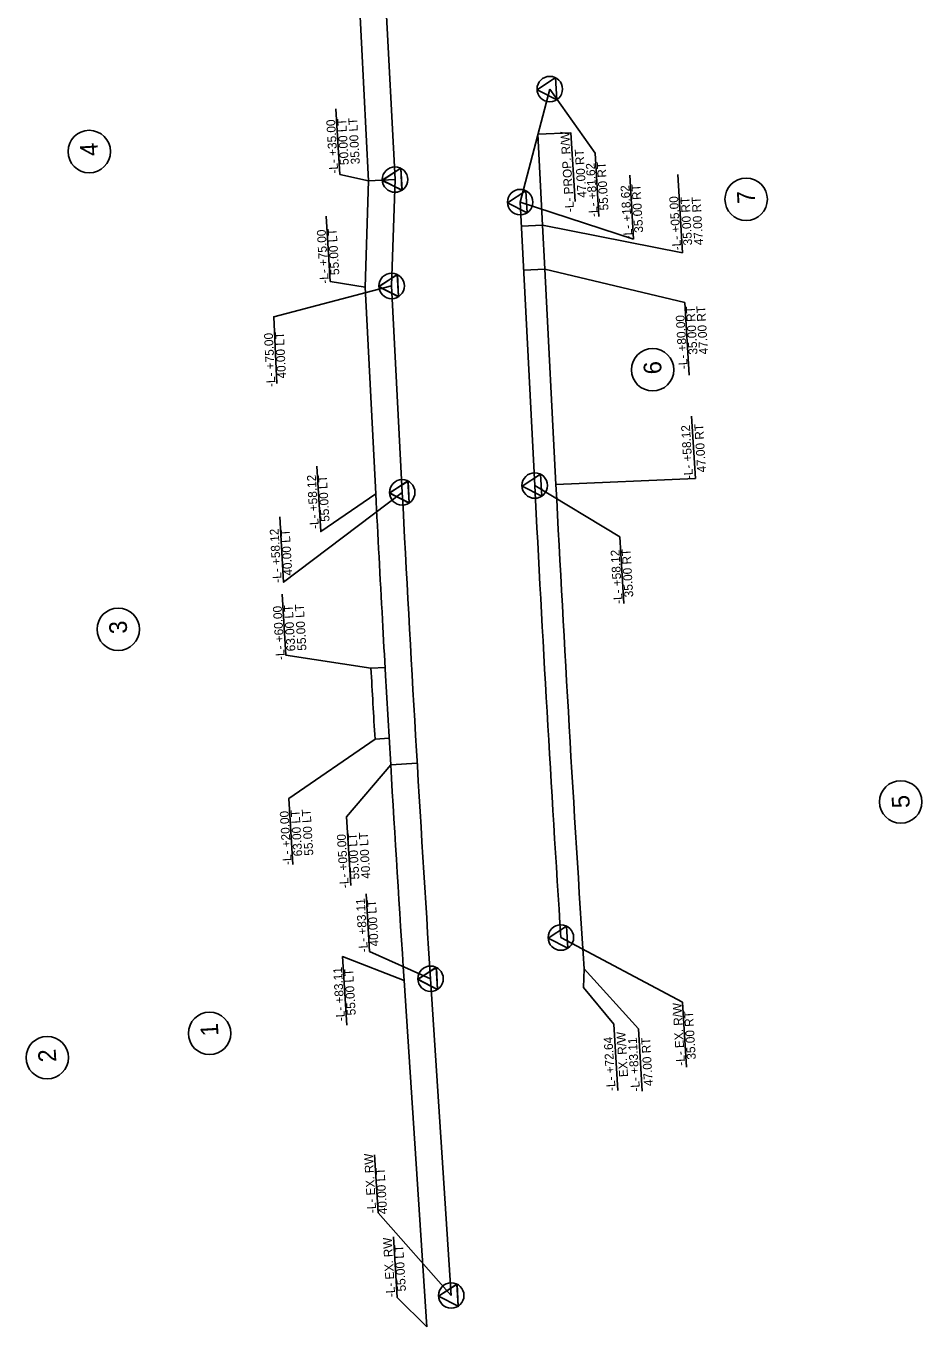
# Model space of a CAD drawing. Extents: x 2368169 to 2369183, y 801414 to 808542.
# Drawn here: x 2368677 to 2369183, y 801414 to 802150 of the extents above; entities that cross this region are included whole.
import ezdxf

# ---------------------------------------------------------------- set-up
doc = ezdxf.new("R2010")
doc.units = 0
for name, color, linetype in [('Prop Easement Construction', 7, 'Continuous'), ('Prop Easement Construction Station Offsets', 7, 'Continuous'), ('Prop Easement Permanent Drainage', 7, 'Continuous'), ('Prop Easement Permanent Drainage Station Offsets', 7, 'Continuous'), ('Prop Easement Permanent Drainage Utility', 7, 'Continuous'), ('Prop Easement Permanent Drainage Utility Station Offsets', 7, 'Continuous'), ('Prop Easement Permanent Utility', 7, 'Continuous'), ('Prop Easement Permanent Utility Station Offsets', 7, 'Continuous'), ('Prop Parcel Number CELL', 7, 'Continuous'), ('Prop Parcel Number Text', 7, 'Continuous'), ('Prop ROW Marker CELL', 7, 'Continuous'), ('Prop ROW RW Lines', 7, 'Continuous'), ('Prop ROW Station Offsets', 7, 'Continuous')]:
    doc.layers.add(name, color=color, linetype=linetype)

msp = doc.modelspace()

# ---------------------------------------------------------------- linework, layer by layer
at = {"layer": 'Prop Easement Construction'}
for p, q in [((2368968.57, 802037.5), (2368965.94, 802088.86)), ((2368976.11, 801890.82), (2368969.86, 802012.53)), ((2368992.07, 801616.92), (2368991.68, 801606.39))]:
    msp.add_line(p, q, dxfattribs=at)
msp.add_arc((2388902.84, 802914.38), 19953, 182.940485, 183.728337, dxfattribs=at)
at = {"layer": 'Prop Easement Construction Station Offsets'}
for p, q in [((2369052.79, 801929.37), (2369054.93, 801894.11)), ((2369054.93, 801894.11), (2368976.11, 801890.82))]:
    msp.add_line(p, q, dxfattribs=at)
for points in [[(2368986.96, 802050.94), (2368984.61, 802089.64), (2368965.94, 802088.86)], [(2369024.85, 801547.71), (2369022.72, 801582.85), (2368992.07, 801616.92)], [(2369011.09, 801548.02), (2369008.81, 801585.56), (2368991.68, 801606.39)]]:
    msp.add_lwpolyline(points, dxfattribs=at)
at = {"layer": 'Prop Easement Permanent Drainage'}
for p, q in [((2368968.57, 802037.5), (2368956.59, 802036.88)), ((2368969.86, 802012.53), (2368968.57, 802037.5)), ((2368969.86, 802012.53), (2368957.87, 802011.92)), ((2368879.53, 801787.33), (2368871.54, 801786.88)), ((2368881.82, 801747.29), (2368873.84, 801746.82))]:
    msp.add_line(p, q, dxfattribs=at)
msp.add_arc((2388902.84, 802914.38), 20063, 183.221583, 183.336175, dxfattribs=at)
at = {"layer": 'Prop Easement Permanent Drainage Station Offsets'}
for p, q in [((2369047.63, 802021.89), (2369044.96, 802066.15)), ((2368968.57, 802037.5), (2369047.63, 802021.89)), ((2368969.86, 802012.53), (2369049.01, 801993.71)), ((2369049.01, 801993.71), (2369051.48, 801952.58))]:
    msp.add_line(p, q, dxfattribs=at)
for points in [[(2368821.28, 801828.73), (2368823.35, 801794.29), (2368871.54, 801786.88)], [(2368827.39, 801675.91), (2368825.14, 801713.27), (2368873.84, 801746.82)]]:
    msp.add_lwpolyline(points, dxfattribs=at)
at = {"layer": 'Prop Easement Permanent Drainage Utility'}
for p, q in [((2368868.25, 802002.31), (2368870.16, 802062.48)), ((2368870.19, 802062.49), (2368885.14, 802063.25)), ((2368874.24, 801885.58), (2368868.25, 802002.31)), ((2368882.71, 801732.27), (2368897.68, 801733.16))]:
    msp.add_line(p, q, dxfattribs=at)
for start, end in [(182.940485, 183.144357), (183.144357, 183.234563), (183.234563, 183.379147)]:
    msp.add_arc((2388902.84, 802914.38), 20055, start, end, dxfattribs=at)
at = {"layer": 'Prop Easement Permanent Drainage Utility Station Offsets'}
for p, q in [((2368846.18, 802042.61), (2368848.41, 802005.55)), ((2368848.41, 802005.55), (2368868.25, 802002.31))]:
    msp.add_line(p, q, dxfattribs=at)
for points in [[(2368851.72, 802103.18), (2368853.95, 802066.12), (2368870.16, 802062.48)], [(2368840.89, 801901.21), (2368843.12, 801864.16), (2368874.24, 801885.58)], [(2368860.1, 801664.06), (2368857.77, 801702.9), (2368882.71, 801732.27)]]:
    msp.add_lwpolyline(points, dxfattribs=at)
at = {"layer": 'Prop Easement Permanent Utility'}
for p, q in [((2368870.16, 802062.48), (2368850.79, 802439.57)), ((2368903.05, 801414.3), (2368890.28, 801610.28))]:
    msp.add_line(p, q, dxfattribs=at)
msp.add_arc((2388902.84, 802914.38), 20055, 183.379147, 183.728337, dxfattribs=at)
at = {"layer": 'Prop Easement Permanent Utility Station Offsets'}
for points in [[(2368857.85, 801584.98), (2368855.51, 801623.83), (2368890.28, 801610.28)], [(2368884.27, 801465.25), (2368886.37, 801430.88), (2368903.05, 801414.3)]]:
    msp.add_lwpolyline(points, dxfattribs=at)
at = {"layer": 'Prop Parcel Number CELL'}
for p, q in [((2368712.29, 802079.1), (2368712.29, 802079.1)), ((2369083.65, 802052.08), (2369083.65, 802052.08)), ((2369030.77, 801955.69), (2369030.77, 801955.69)), ((2368728.69, 801808.88), (2368728.69, 801808.88)), ((2369171.02, 801711.28), (2369171.02, 801711.28)), ((2368780.32, 801580.35), (2368780.32, 801580.35)), ((2368688.56, 801566.63), (2368688.56, 801566.63))]:
    msp.add_line(p, q, dxfattribs=at)
for centre in [(2368712.29, 802079.1), (2369083.65, 802052.08), (2369030.77, 801955.69), (2368728.69, 801808.88), (2369171.02, 801711.28), (2368780.32, 801580.35), (2368688.56, 801566.63)]:
    msp.add_circle(centre, 12, dxfattribs=at)
at = {"layer": 'Prop ROW Marker CELL'}
for p, q in [((2368972.63, 802114.43), (2368972.63, 802114.43)), ((2368972.63, 802114.43), (2368972.63, 802114.43)), ((2368885.14, 802063.25), (2368885.14, 802063.25)), ((2368885.14, 802063.25), (2368885.14, 802063.25)), ((2368955.89, 802050.49), (2368955.89, 802050.49)), ((2368955.89, 802050.49), (2368955.89, 802050.49)), ((2368883.23, 802003.08), (2368883.23, 802003.08)), ((2368883.23, 802003.08), (2368883.23, 802003.08)), ((2368964.12, 801890.2), (2368964.12, 801890.2)), ((2368964.12, 801890.2), (2368964.12, 801890.2)), ((2368889.22, 801886.35), (2368889.22, 801886.35)), ((2368889.22, 801886.35), (2368889.22, 801886.35)), ((2368978.9, 801634.55), (2368978.9, 801634.55)), ((2368978.9, 801634.55), (2368978.9, 801634.55)), ((2368905.25, 801611.26), (2368905.25, 801611.26)), ((2368905.25, 801611.26), (2368905.25, 801611.26)), ((2368916.92, 801432.11), (2368916.92, 801432.11)), ((2368916.92, 801432.11), (2368916.92, 801432.11))]:
    msp.add_line(p, q, dxfattribs=at)
for points in [[(2368976.6, 802108.41), (2368965.44, 802114), (2368975.85, 802120.89)], [(2368976.6, 802108.41), (2368965.44, 802114), (2368975.85, 802120.89)], [(2368889.02, 802057.17), (2368877.95, 802062.93), (2368888.46, 802069.66)], [(2368889.11, 802057.23), (2368877.96, 802062.82), (2368888.36, 802069.71)], [(2368959.86, 802044.46), (2368948.7, 802050.05), (2368959.11, 802056.94)], [(2368959.86, 802044.46), (2368948.7, 802050.05), (2368959.11, 802056.94)], [(2368887.1, 801996.99), (2368876.03, 802002.75), (2368886.54, 802009.48)], [(2368887.2, 801997.05), (2368876.04, 802002.64), (2368886.44, 802009.53)], [(2368968.09, 801884.18), (2368956.94, 801889.77), (2368967.34, 801896.65)], [(2368968.09, 801884.18), (2368956.94, 801889.77), (2368967.34, 801896.65)], [(2368893.1, 801880.27), (2368882.03, 801886.03), (2368892.54, 801892.76)], [(2368893.19, 801880.33), (2368882.04, 801885.92), (2368892.44, 801892.81)], [(2368982.87, 801628.53), (2368971.71, 801634.12), (2368982.12, 801641)], [(2368982.87, 801628.53), (2368971.71, 801634.12), (2368982.12, 801641)], [(2368909.22, 801605.24), (2368898.06, 801610.83), (2368908.47, 801617.71)], [(2368909.13, 801605.18), (2368898.06, 801610.94), (2368908.57, 801617.66)], [(2368920.8, 801426.03), (2368909.73, 801431.79), (2368920.24, 801438.52)], [(2368920.89, 801426.09), (2368909.74, 801431.68), (2368920.14, 801438.57)]]:
    msp.add_lwpolyline(points, close=True, dxfattribs=at)
for centre in [(2368972.63, 802114.43), (2368885.14, 802063.25), (2368955.89, 802050.49), (2368883.23, 802003.08), (2368964.12, 801890.2), (2368889.22, 801886.35), (2368978.9, 801634.55), (2368905.25, 801611.26), (2368916.92, 801432.11)]:
    msp.add_circle(centre, 7.2, dxfattribs=at)
at = {"layer": 'Prop ROW RW Lines'}
for p, q in [((2368885.14, 802063.25), (2368865.77, 802440.34)), ((2368972.63, 802114.43), (2368955.89, 802050.49)), ((2368883.23, 802003.08), (2368885.14, 802063.25)), ((2368964.12, 801890.2), (2368955.89, 802050.49)), ((2368889.22, 801886.35), (2368883.23, 802003.08)), ((2368916.92, 801432.11), (2368905.25, 801611.26))]:
    msp.add_line(p, q, dxfattribs=at)
for radius, end in [(19965, 183.675386), (20040, 183.728337)]:
    msp.add_arc((2388902.84, 802914.38), radius, 182.940485, end, dxfattribs=at)
at = {"layer": 'Prop ROW Station Offsets'}
for p, q in [((2368998.26, 802078.18), (2368972.63, 802114.43)), ((2369000.42, 802042.31), (2368998.26, 802078.18)), ((2369020.05, 802029.51), (2369017.87, 802065.71)), ((2369020.05, 802029.51), (2368955.89, 802050.49)), ((2369047.63, 801597.97), (2368978.9, 801634.55)), ((2369049.84, 801561.31), (2369047.63, 801597.97)), ((2368873.55, 801511.7), (2368875.53, 801478.77)), ((2368875.53, 801478.77), (2368916.92, 801432.11))]:
    msp.add_line(p, q, dxfattribs=at)
for points in [[(2368818.41, 801947.87), (2368816.57, 801985.67), (2368883.23, 802003.08)], [(2369014.45, 801823.5), (2369012.18, 801861.19), (2368964.12, 801890.2)], [(2368819.95, 801872.54), (2368822.18, 801835.48), (2368889.22, 801886.35)], [(2368868.81, 801659.27), (2368870.77, 801626.67), (2368905.25, 801611.26)]]:
    msp.add_lwpolyline(points, dxfattribs=at)

# ---------------------------------------------------------------- texts
at = {"layer": 'Prop Easement Construction Station Offsets'}
for s, p in [('-L- PROP. R/W', (2368986.37, 802045)), ('47.00 RT', (2368993.39, 802053.09)), ('-L- +58.12', (2369053.68, 801893.93)), ('47.00 RT', (2369060.97, 801897.75)), ('EX. R/W', (2369016.88, 801555.79)), ('-L- +72.64', (2369009.85, 801547.91)), ('-L- +83.11', (2369023.61, 801547.56)), ('47.00 RT', (2369030.94, 801550.67))]:
    msp.add_text(s, height=5, rotation=93.47163, dxfattribs=at).set_placement(p)
at = {"layer": 'Prop Easement Permanent Drainage Station Offsets'}
for s, p in [('-L- +05.00', (2369046.93, 802023.39)), ('35.00 RT', (2369053.17, 802026.16)), ('47.00 RT', (2369059.4, 802026.26)), ('-L- +80.00', (2369050.61, 801956.16)), ('35.00 RT', (2369056.17, 801964.38)), ('47.00 RT', (2369062.11, 801964.49)), ('55.00 LT', (2368835.09, 801796.95)), ('-L- +60.00', (2368822.88, 801791.67)), ('63.00 LT', (2368828.85, 801796.58)), ('-L- +20.00', (2368826.77, 801675.72)), ('63.00 LT', (2368832.74, 801680.63)), ('55.00 LT', (2368838.98, 801681))]:
    msp.add_text(s, height=5, rotation=93.44297, dxfattribs=at).set_placement(p)
at = {"layer": 'Prop Easement Permanent Drainage Utility Station Offsets'}
for s, p in [('-L- +35.00', (2368853.07, 802066.76)), ('50.00 LT', (2368859.04, 802071.66)), ('35.00 LT', (2368865.27, 802072.04)), ('-L- +75.00', (2368847.73, 802004.5)), ('55.00 LT', (2368853.69, 802009.4)), ('-L- +58.12', (2368842.15, 801865.8)), ('55.00 LT', (2368848.16, 801869.83)), ('-L- +05.00', (2368859.05, 801662.63)), ('55.00 LT', (2368865.01, 801667.53)), ('40.00 LT', (2368871.25, 801667.91))]:
    msp.add_text(s, height=5, rotation=93.44297, dxfattribs=at).set_placement(p)
at = {"layer": 'Prop Easement Permanent Utility Station Offsets'}
for s, p in [('-L- +83.11', (2368856.92, 801587.37)), ('55.00 LT', (2368862.98, 801590.69)), ('-L- EX. RW', (2368885.28, 801431.29)), ('55.00 LT', (2368891.35, 801434.52))]:
    msp.add_text(s, height=5, rotation=93.44297, dxfattribs=at).set_placement(p)
at = {"layer": 'Prop Parcel Number Text'}
for s, p in [('4', (2368717.43, 802076.82)), ('7', (2369088.8, 802049.83)), ('6', (2369035.92, 801953.38)), ('3', (2368733.83, 801806.59)), ('5', (2369176.23, 801707.98)), ('1', (2368785.41, 801578.97)), ('2', (2368693.71, 801564.34))]:
    msp.add_text(s, height=10, rotation=93.44297, dxfattribs=at).set_placement(p)
at = {"layer": 'Prop ROW Station Offsets'}
for s, rotation, p in [('-L- +81.62', 93.44297, (2368999.8, 802042.2)), ('55.00 RT', 93.44297, (2369005.84, 802045.94)), ('-L- +18.62', 93.44297, (2369019.41, 802029.6)), ('35.00 RT', 93.44297, (2369025.45, 802033.34)), ('-L- +75.00', 92.79291, (2368817.55, 801946.02)), ('40.00 LT', 92.79291, (2368823.57, 801950.85)), ('-L- +58.12', 93.44297, (2368821.12, 801835.35)), ('40.00 LT', 93.44297, (2368827.14, 801839.39)), ('-L- +58.12', 93.44297, (2369013.83, 801823.4)), ('35.00 RT', 93.44297, (2369019.86, 801827.14)), ('-L- +83.11', 93.44297, (2368869.83, 801626.32)), ('40.00 LT', 93.44297, (2368875.9, 801629.64)), ('-L- EX. R/W', 93.44297, (2369049.16, 801562.19)), ('35.00 RT', 93.44297, (2369055.21, 801565.67)), ('-L- EX. RW', 93.44297, (2368874.57, 801478.82)), ('40.00 LT', 93.44297, (2368880.77, 801478.22))]:
    msp.add_text(s, height=5, rotation=rotation, dxfattribs=at).set_placement(p)

doc.saveas('drawing.dxf')
